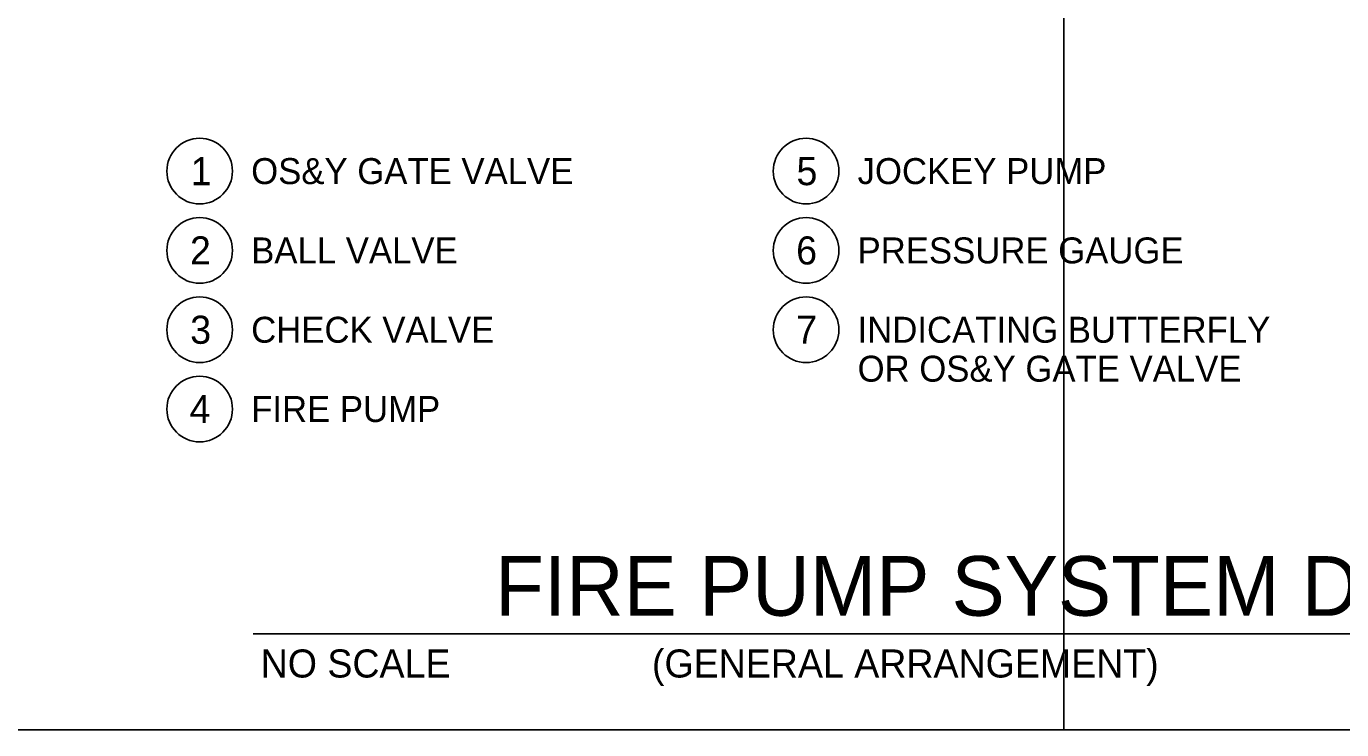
# Model space of a CAD drawing. Extents: x 10442.9 to 10533.9, y 10030 to 10079.1.
# Drawn here: x 10461.8 to 10495.58, y 10029.98 to 10048.04 of the extents above; entities that cross this region are included whole.
import ezdxf

# ---------------------------------------------------------------- set-up
doc = ezdxf.new("R2010")
doc.units = 0
for name, color, linetype in [('G-ANNO-CELL', 7, 'Continuous'), ('G-ANNO-NPLT', 7, 'Continuous'), ('G-ANNO-SYMB', 7, 'Continuous'), ('G-DETL-TEXT', 7, 'Continuous')]:
    doc.layers.add(name, color=color, linetype=linetype)

msp = doc.modelspace()

# ---------------------------------------------------------------- linework, layer by layer
at = {"layer": 'G-ANNO-CELL'}
msp.add_line((10467.62, 10032.437), (10509.274, 10032.437), dxfattribs=at)
at = {"layer": 'G-ANNO-NPLT'}
for points in [[(10442.947, 10029.978), (10442.947, 10079.12), (10488.447, 10079.12), (10488.447, 10029.978)], [(10488.447, 10029.978), (10488.447, 10079.12), (10533.947, 10079.12), (10533.947, 10029.978)]]:
    msp.add_lwpolyline(points, close=True, dxfattribs=at)
at = {"layer": 'G-ANNO-SYMB'}
for centre in [(10466.249, 10044.322), (10481.822, 10044.322), (10466.249, 10042.285), (10481.822, 10042.285), (10466.249, 10040.249), (10481.822, 10040.249), (10466.249, 10038.212)]:
    msp.add_circle(centre, 0.843, dxfattribs=at)

# ---------------------------------------------------------------- texts
at = {"layer": 'G-ANNO-CELL'}
for s, height, p in [('FIRE PUMP SYSTEM DETAIL', 1.53173, (10473.838, 10032.904)), ('NO SCALE', 0.7208, (10467.816, 10031.318)), ('(GENERAL ARRANGEMENT)', 0.72081, (10477.865, 10031.318))]:
    msp.add_text(s, height=height, dxfattribs=at).set_placement(p)
at = {"layer": 'G-ANNO-SYMB'}
for s, p in [('1', (10466.018, 10043.961)), ('5', (10481.577, 10043.961)), ('2', (10466, 10041.925)), ('6', (10481.568, 10041.925)), ('3', (10466.006, 10039.888)), ('7', (10481.57, 10039.888)), ('4', (10465.991, 10037.852))]:
    msp.add_text(s, height=0.721, dxfattribs=at).set_placement(p)
at = {"layer": 'G-DETL-TEXT'}
for s, height, p in [('OS&Y GATE VALVE', 0.66667, (10467.572, 10043.989)), ('JOCKEY PUMP', 0.66667, (10483.146, 10043.989)), ('BALL VALVE', 0.6667, (10467.572, 10041.952)), ('PRESSURE GAUGE', 0.66667, (10483.146, 10041.952)), ('CHECK VALVE', 0.66667, (10467.572, 10039.915)), ('INDICATING BUTTERFLY', 0.66667, (10483.146, 10039.915)), ('OR OS&Y GATE VALVE', 0.66667, (10483.146, 10038.915)), ('FIRE PUMP', 0.6667, (10467.572, 10037.879))]:
    msp.add_text(s, height=height, dxfattribs=at).set_placement(p)

doc.saveas('drawing.dxf')
